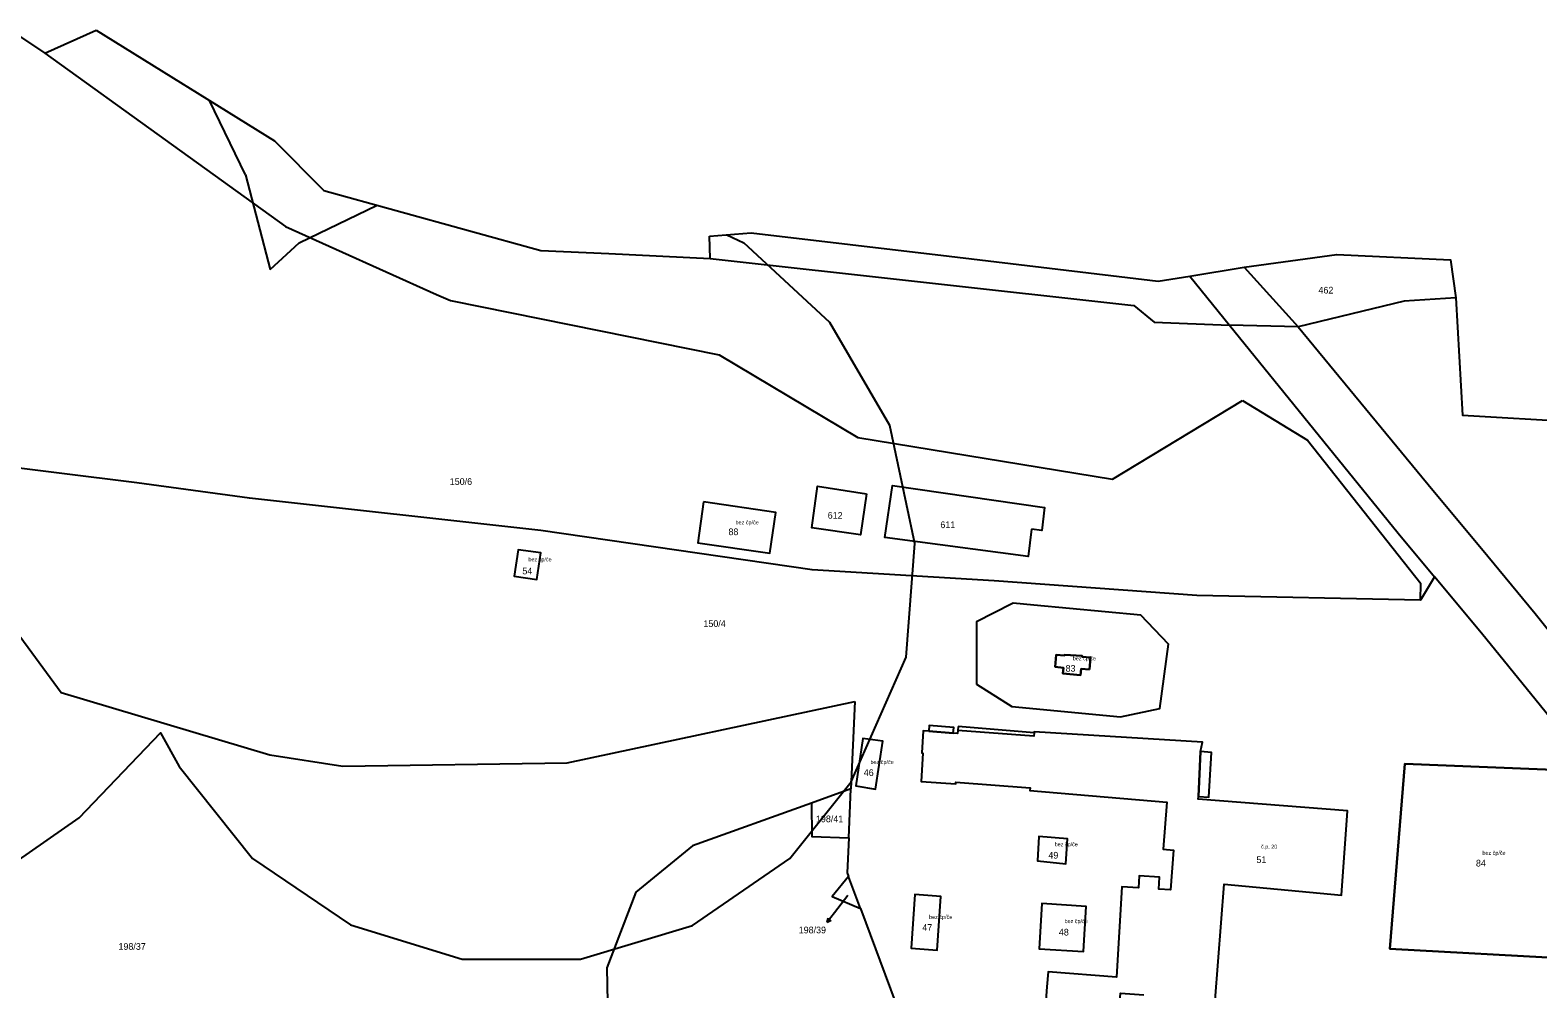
# Model space of a CAD drawing. Extents: x -887272 to -877616, y -1026687 to -1019819.
# Drawn here: x -880486.8 to -880102.6, y -1020208.1 to -1019963.7 of the extents above; entities that cross this region are included whole.
import ezdxf

# ---------------------------------------------------------------- set-up
doc = ezdxf.new("R2010")
doc.units = 0
for name, color, linetype in [('Definiční body', 7, 'Continuous'), ('Hranice parcel', 7, 'Continuous'), ('Parcelní čísla', 7, 'Continuous'), ('Polygon budovy', 7, 'Continuous'), ('Pop  PČ popisy', 7, 'Continuous'), ('Vnitřní kresba', 7, 'Continuous')]:
    doc.layers.add(name, color=color, linetype=linetype)

msp = doc.modelspace()

# ---------------------------------------------------------------- linework, layer by layer
at = {"layer": 'Hranice parcel'}
for p, q in [((-880470.01, -1019963.68), (-880424.53, -1019991.9)), ((-880424.53, -1019991.9), (-880411.97, -1020004.58)), ((-880411.97, -1020004.58), (-880356.66, -1020019.88)), ((-880313.68, -1020016.21), (-880303.06, -1020015.38)), ((-880313.53, -1020021.89), (-880313.68, -1020016.21)), ((-880356.66, -1020019.88), (-880339.38, -1020020.63)), ((-880339.38, -1020020.63), (-880313.53, -1020021.89)), ((-880191.22, -1020026.44), (-880177.44, -1020024.1)), ((-880163.65, -1020039.32), (-880181.11, -1020038.89)), ((-880276.63, -1020134.84), (-880277.64, -1020157.16)), ((-880277.64, -1020157.16), (-880287.69, -1020160.77)), ((-880278.21, -1020169.62), (-880277.64, -1020157.16)), ((-880275.21, -1020187.64), (-880278.26, -1020179.47))]:
    msp.add_line(p, q, dxfattribs=at)
for points in [[(-880490.55, -1019964.56), (-880483.11, -1019969.52), (-880470.01, -1019963.68)], [(-880303.06, -1020015.38), (-880252.6, -1020021.33), (-880199.31, -1020027.67), (-880191.22, -1020026.44)], [(-880313.53, -1020021.89), (-880205.55, -1020033.87), (-880200.38, -1020038.13), (-880181.11, -1020038.89)], [(-880177.44, -1020024.1), (-880153.83, -1020020.89), (-880124.84, -1020022.22), (-880123.46, -1020031.92)], [(-880123.46, -1020031.92), (-880136.65, -1020032.77), (-880163.65, -1020039.32)], [(-880123.46, -1020031.92), (-880121.79, -1020061.83), (-880092.81, -1020063.54), (-880094.81, -1020080.54), (-880096.99, -1020100.28)], [(-880181.11, -1020038.89), (-880138.13, -1020091.96), (-880128.9, -1020103.08)], [(-880163.65, -1020039.32), (-880129.35, -1020080.97), (-880116.9, -1020095.84), (-880103.23, -1020112.38), (-880070.49, -1020153.39), (-880028.73, -1020206.59)], [(-880128.9, -1020103.08), (-880132.45, -1020109.03), (-880189.45, -1020107.84), (-880241.14, -1020104.11), (-880287.51, -1020101.32), (-880356.63, -1020091.22), (-880430.92, -1020082.98), (-880459.65, -1020079.14), (-880540.91, -1020069)], [(-880273.66, -1020081.92), (-880275.17, -1020092.35), (-880287.64, -1020090.56), (-880286.12, -1020079.97), (-880273.66, -1020081.92)], [(-880231.58, -1020090.94), (-880232.48, -1020097.91), (-880268.98, -1020093.02), (-880267.01, -1020079.77), (-880228.29, -1020085.37), (-880228.99, -1020091.28), (-880231.58, -1020090.94)], [(-880315.18, -1020083.99), (-880316.67, -1020094.43), (-880298.27, -1020097.07), (-880296.78, -1020086.7), (-880315.18, -1020083.99)], [(-880357.66, -1020103.76), (-880356.68, -1020096.98), (-880362.46, -1020096.17), (-880363.47, -1020102.9), (-880357.66, -1020103.76)], [(-880502.38, -1020102.49), (-880497.06, -1020107.99), (-880478.95, -1020132.59), (-880425.73, -1020148.42), (-880407.16, -1020151.31), (-880349.97, -1020150.48), (-880276.63, -1020134.84)], [(-880079.85, -1020163.08), (-880116.94, -1020117.46), (-880128.9, -1020103.08)], [(-880236.63, -1020109.97), (-880245.65, -1020114.53), (-880245.59, -1020130.44), (-880236.66, -1020136.12), (-880208.94, -1020138.76), (-880198.91, -1020136.64), (-880196.71, -1020120.23), (-880203.71, -1020112.84), (-880230.98, -1020110.31), (-880236.31, -1020109.81), (-880236.63, -1020109.97)], [(-880250.46, -1020143), (-880251.55, -1020142.92), (-880251.42, -1020141.46), (-880257.66, -1020140.95), (-880257.8, -1020142.46), (-880259.26, -1020142.35), (-880259.6, -1020147.96), (-880259.31, -1020148), (-880259.75, -1020155.28), (-880250.91, -1020155.86), (-880250.88, -1020155.4), (-880231.94, -1020156.84), (-880232, -1020157.58)], [(-880250.27, -1020141.21), (-880250.35, -1020142.23), (-880250.46, -1020143)], [(-880230.94, -1020142.57), (-880230.96, -1020142.81), (-880250.27, -1020141.21)], [(-880182.51, -1020181.47), (-880152.59, -1020184.24), (-880151.07, -1020162.72), (-880189.12, -1020159.73), (-880189.08, -1020159.08), (-880186.4, -1020159.21), (-880185.71, -1020147.84), (-880188.51, -1020147.62), (-880188.06, -1020145.19), (-880230.94, -1020142.57)], [(-880269.51, -1020144.98), (-880274.57, -1020144.27), (-880276.42, -1020156.38), (-880271.37, -1020157.21), (-880269.51, -1020144.98)], [(-880140.25, -1020197.9), (-880136.43, -1020150.78), (-880092.16, -1020152.51), (-880093.77, -1020200.46), (-880140.25, -1020197.9)], [(-880232, -1020157.58), (-880197.16, -1020160.55), (-880198.04, -1020172.53), (-880195.41, -1020172.75), (-880196.16, -1020182.86)], [(-880287.69, -1020160.77), (-880318.03, -1020171.68), (-880332.46, -1020183.44), (-880339.85, -1020202.75), (-880338.05, -1020295.44)], [(-880287.69, -1020160.77), (-880287.61, -1020169.31), (-880278.21, -1020169.62)], [(-880278.21, -1020169.62), (-880278.61, -1020178.52), (-880278.26, -1020179.47)], [(-880229.77, -1020169.3), (-880230.08, -1020175.45), (-880222.86, -1020176.28), (-880222.46, -1020169.89), (-880229.77, -1020169.3)], [(-880278.26, -1020179.47), (-880282.45, -1020184.57), (-880275.21, -1020187.64)], [(-880196.16, -1020182.86), (-880199.17, -1020182.68), (-880198.99, -1020179.63), (-880204.19, -1020179.32), (-880204.37, -1020182.37), (-880208.6, -1020182.12), (-880209.97, -1020205.13), (-880227.34, -1020203.79), (-880227.69, -1020207.65), (-880228.65, -1020220.35), (-880209.87, -1020221.77), (-880208.89, -1020209.22), (-880202.95, -1020209.66)], [(-880254.68, -1020184.54), (-880261.35, -1020184.05), (-880262.26, -1020197.71), (-880255.63, -1020198.24), (-880254.68, -1020184.54)], [(-880179.41, -1020211.39), (-880184.76, -1020211), (-880182.51, -1020181.47)], [(-880275.21, -1020187.64), (-880258.76, -1020231.77), (-880145.16, -1020240.12)], [(-880217.69, -1020187.09), (-880229, -1020186.35), (-880229.67, -1020197.9), (-880218.4, -1020198.56), (-880217.69, -1020187.09)]]:
    msp.add_lwpolyline(points, dxfattribs=at)
at = {"layer": 'Polygon budovy'}
for points in [[(-880315.18, -1020083.99), (-880316.67, -1020094.43), (-880298.27, -1020097.07), (-880296.78, -1020086.7)], [(-880363.47, -1020102.9), (-880357.66, -1020103.76), (-880356.68, -1020096.98), (-880362.46, -1020096.17)], [(-880216.79, -1020126.73), (-880216.55, -1020123.67), (-880218.7, -1020123.5), (-880218.68, -1020123.25), (-880223.19, -1020122.92), (-880223.22, -1020123.16), (-880225.35, -1020122.99), (-880225.58, -1020126.04), (-880223.44, -1020126.25), (-880223.59, -1020127.76), (-880219.11, -1020128.11), (-880218.99, -1020126.56)], [(-880274.57, -1020144.27), (-880276.42, -1020156.38), (-880271.37, -1020157.21), (-880269.51, -1020144.98)], [(-880092.16, -1020152.51), (-880136.43, -1020150.78), (-880140.25, -1020197.9), (-880093.77, -1020200.46)], [(-880222.86, -1020176.28), (-880222.46, -1020169.89), (-880229.77, -1020169.3), (-880230.08, -1020175.45)], [(-880262.26, -1020197.71), (-880255.63, -1020198.24), (-880254.68, -1020184.54), (-880261.35, -1020184.05)], [(-880218.4, -1020198.56), (-880217.69, -1020187.09), (-880229, -1020186.35), (-880229.67, -1020197.9)]]:
    msp.add_lwpolyline(points, close=True, dxfattribs=at)
msp.add_lwpolyline([(-880184.76, -1020211), (-880182.51, -1020181.47), (-880152.59, -1020184.24), (-880151.07, -1020162.72), (-880189.12, -1020159.73), (-880189.08, -1020159.08), (-880188.51, -1020147.62), (-880188.06, -1020145.19), (-880230.94, -1020142.57), (-880230.96, -1020142.81), (-880231.04, -1020143.7), (-880250.35, -1020142.23), (-880250.46, -1020143), (-880251.55, -1020142.92), (-880257.8, -1020142.46), (-880259.26, -1020142.35), (-880259.6, -1020147.96), (-880259.31, -1020148), (-880259.75, -1020155.28), (-880250.91, -1020155.86), (-880250.88, -1020155.4), (-880231.94, -1020156.84), (-880232, -1020157.58), (-880197.16, -1020160.55), (-880198.04, -1020172.53), (-880195.41, -1020172.75), (-880196.16, -1020182.86), (-880199.17, -1020182.68), (-880198.99, -1020179.63), (-880204.19, -1020179.32), (-880204.37, -1020182.37), (-880208.6, -1020182.12), (-880209.97, -1020205.13), (-880227.34, -1020203.79), (-880227.69, -1020207.65), (-880228.65, -1020220.35)], dxfattribs=at)
at = {"layer": 'Pop  PČ popisy'}
for p, q in [((-880278.46, -1020184.29), (-880281.85, -1020188.73)), ((-880281.85, -1020188.73), (-880283.66, -1020191.13)), ((-880283.66, -1020191.13), (-880283.45, -1020190.03)), ((-880283.66, -1020191.13), (-880282.65, -1020190.63))]:
    msp.add_line(p, q, dxfattribs=at)
at = {"layer": 'Vnitřní kresba'}
for p, q in [((-880483.11, -1019969.52), (-880421.79, -1020013.78)), ((-880431.93, -1020000.59), (-880441.16, -1019981.58)), ((-880431.93, -1020000.59), (-880425.69, -1020024.68)), ((-880418.3, -1020017.94), (-880398.37, -1020008.34)), ((-880421.79, -1020013.78), (-880383.29, -1020031.1)), ((-880309.23, -1020015.86), (-880304.9, -1020017.91)), ((-880425.69, -1020024.68), (-880418.3, -1020017.93)), ((-880191.22, -1020026.44), (-880181.11, -1020038.89)), ((-880177.44, -1020024.1), (-880163.65, -1020039.32)), ((-880383.29, -1020031.1), (-880379.69, -1020032.59)), ((-880379.69, -1020032.59), (-880311.22, -1020046.5)), ((-880311.22, -1020046.5), (-880275.89, -1020067.58)), ((-880211, -1020078.14), (-880177.81, -1020058.11)), ((-880177.81, -1020058.11), (-880161.24, -1020068.23)), ((-880275.89, -1020067.58), (-880211, -1020078.14)), ((-880161.24, -1020068.23), (-880132.37, -1020104.75)), ((-880132.45, -1020109.03), (-880132.37, -1020104.75)), ((-880225.58, -1020126.04), (-880225.35, -1020122.99)), ((-880225.35, -1020122.99), (-880223.22, -1020123.16)), ((-880223.22, -1020123.16), (-880223.19, -1020122.92)), ((-880223.19, -1020122.92), (-880218.68, -1020123.25)), ((-880218.68, -1020123.25), (-880218.7, -1020123.5)), ((-880218.7, -1020123.5), (-880216.55, -1020123.67)), ((-880223.44, -1020126.25), (-880225.58, -1020126.04)), ((-880223.59, -1020127.76), (-880223.44, -1020126.25)), ((-880218.99, -1020126.56), (-880219.11, -1020128.11)), ((-880216.79, -1020126.73), (-880218.99, -1020126.56)), ((-880216.55, -1020123.67), (-880216.79, -1020126.73)), ((-880219.11, -1020128.11), (-880223.59, -1020127.76)), ((-880257.8, -1020142.46), (-880251.55, -1020142.92)), ((-880231.04, -1020143.7), (-880250.35, -1020142.23)), ((-880230.96, -1020142.81), (-880231.04, -1020143.7)), ((-880188.51, -1020147.62), (-880189.08, -1020159.08))]:
    msp.add_line(p, q, dxfattribs=at)
for points in [[(-880263.6, -1020123.56), (-880261.31, -1020094.54), (-880267.72, -1020064.46), (-880283, -1020038.24), (-880304.9, -1020017.91)], [(-880293.2, -1020174.89), (-880277.57, -1020155.32), (-880263.6, -1020123.56)], [(-880615.29, -1020193.51), (-880585.87, -1020199.54), (-880556.01, -1020199.53), (-880526.59, -1020193.5), (-880498.86, -1020181.6), (-880474.31, -1020164.53), (-880453.64, -1020142.82), (-880448.85, -1020151.39), (-880430.15, -1020174.89), (-880405.16, -1020191.79), (-880376.74, -1020200.57), (-880346.52, -1020200.57), (-880318.05, -1020191.93), (-880293.2, -1020174.89)]]:
    msp.add_lwpolyline(points, dxfattribs=at)

# ---------------------------------------------------------------- texts
at = {"layer": 'Definiční body'}
for s, p in [('bez čp/če', (-880307.04, -1020089.69)), ('bez čp/če', (-880359.83, -1020099.12)), ('bez čp/če', (-880221.09, -1020124.35)), ('bez čp/če', (-880272.64, -1020150.82)), ('bez čp/če', (-880225.71, -1020171.76)), ('č.p. 20', (-880173.11, -1020172.37)), ('bez čp/če', (-880116.69, -1020173.96)), ('bez čp/če', (-880257.71, -1020190.3)), ('bez čp/če', (-880223.18, -1020191.37))]:
    msp.add_text(s, height=1, dxfattribs=at).set_placement(p)
at = {"layer": 'Parcelní čísla'}
for s, p in [('462', (-880158.48, -1020030.83)), ('150/6', (-880379.88, -1020079.63)), ('612', (-880283.55, -1020088.26)), ('611', (-880254.84, -1020090.65)), ('88', (-880308.85, -1020092.44)), ('54', (-880361.38, -1020102.43)), ('150/4', (-880315.23, -1020115.86)), ('83', (-880222.93, -1020127.25)), ('46', (-880274.37, -1020153.84)), ('198/41', (-880286.55, -1020165.64)), ('49', (-880227.31, -1020174.91)), ('51', (-880174.28, -1020176.04)), ('84', (-880118.34, -1020176.92)), ('198/39', (-880290.94, -1020193.96)), ('47', (-880259.44, -1020193.32)), ('198/37', (-880464.32, -1020198.17)), ('48', (-880224.64, -1020194.52))]:
    msp.add_text(s, height=1.7, dxfattribs=at).set_placement(p)

doc.saveas('drawing.dxf')
